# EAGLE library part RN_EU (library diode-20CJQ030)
Chip Resistor Array's from various manufactures
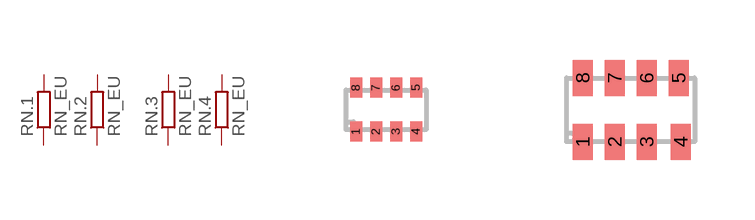
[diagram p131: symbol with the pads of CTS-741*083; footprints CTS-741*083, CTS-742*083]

Designator prefix RN; gates .1=RN-EU .2=RN-EU .3=RN-EU .4=RN-EU

## RN_EU-1  [CTS-741*083]
1  .1:1  pas
2  .2:1  pas
3  .3:1  pas
4  .4:1  pas
5  .4:2  pas
6  .3:2  pas
7  .2:2  pas
8  .1:2  pas

## RN_EU-2  [CTS-742*083]
Pads as for CTS-741*083

## RN_EU-3  [CTS-743*083]
Pads as for CTS-741*083

## RN_EU-4  [CTS-744*083]
Pads as for CTS-741*083

## RN_EU-5  [EXB-28V]
Pads as for CTS-741*083

## RN_EU-6  [EXB-38V]
Pads as for CTS-741*083

## RN_EU-7  [EXB-V8V]
Pads as for CTS-741*083

## Footprint CTS-741*083 (pad centres in mm)
CTS Resistor Chip Arrays 402
smd 0.3 x 0.5: 1 -0.75,-0.55; 2 -0.25,-0.55; 3 0.25,-0.55; 4 0.75,-0.55; 5 0.75,0.55; 6 0.25,0.55; 7 -0.25,0.55; 8 -0.75,0.55

## Footprint CTS-742*083 (pad centres in mm)
CTS Resistor Chip Arrays 603
smd 0.5 x 0.9: 1 -1.2,-0.8; 2 -0.4,-0.8; 3 0.4,-0.8; 4 1.25,-0.8; 5 1.2,0.8; 6 0.4,0.8; 7 -0.4,0.8; 8 -1.2,0.8

## Footprint CTS-743*083 (pad centres in mm)
CTS Resistor Chip Arrays 805
smd 0.8 x 1: 1 -1.905,-1; 2 -0.635,-1; 3 0.635,-1; 4 1.905,-1; 5 1.905,1; 6 0.635,1; 7 -0.635,1; 8 -1.905,1

## Footprint CTS-744*083 (pad centres in mm)
CTS Resistor Chip Arrays 1206
smd 0.8 x 1: 1 -1.905,-1.6; 2 -0.635,-1.6; 3 0.635,-1.6; 4 1.905,-1.6; 5 1.905,1.6; 6 0.635,1.6; 7 -0.635,1.6; 8 -1.905,1.6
